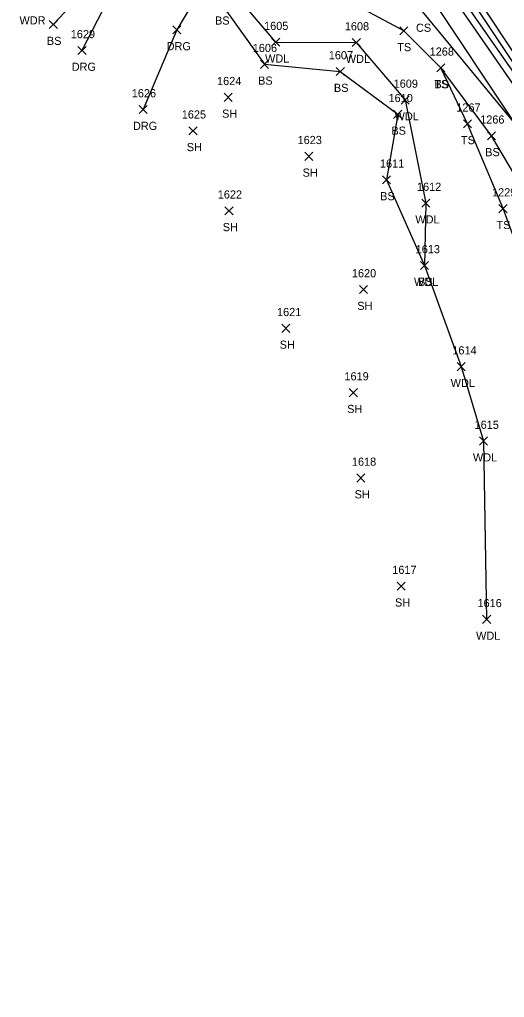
# Model space of a CAD drawing. Extents: x 1501299 to 1502485, y 381423 to 383765.
# Drawn here: x 1501632.6 to 1501751.5, y 382849.9 to 383089.7 of the extents above; entities that cross this region are included whole.
import ezdxf

# ---------------------------------------------------------------- set-up
doc = ezdxf.new("R2010")
doc.units = 0
for name, color, linetype in [('L_A', 7, 'Continuous'), ('L_I', 7, 'Continuous'), ('L_TIC', 7, 'Continuous'), ('LAWA', 7, 'Continuous'), ('LELB', 7, 'Continuous'), ('PET', 7, 'Continuous'), ('R_A', 7, 'Continuous'), ('R_I', 7, 'Continuous'), ('R_TIC', 7, 'Continuous'), ('RDG', 7, 'Continuous')]:
    doc.layers.add(name, color=color, linetype=linetype)

msp = doc.modelspace()

# ---------------------------------------------------------------- linework, layer by layer
at = {"layer": 'L_TIC'}
for points in [[(1501639.86, 383087.47), (1501641.86, 383089.47)], [(1501641.86, 383087.47), (1501639.86, 383089.47)], [(1501725.8, 383085.93), (1501727.8, 383087.93)], [(1501727.8, 383085.93), (1501725.8, 383087.93)], [(1501694.37, 383083.14), (1501696.37, 383085.14)], [(1501696.37, 383083.14), (1501694.37, 383085.14)], [(1501714.16, 383083.04), (1501716.16, 383085.04)], [(1501716.16, 383083.04), (1501714.16, 383085.04)], [(1501691.64, 383077.72), (1501693.64, 383079.72)], [(1501693.64, 383077.72), (1501691.64, 383079.72)], [(1501734.88, 383076.84), (1501736.88, 383078.84)], [(1501736.88, 383076.84), (1501734.88, 383078.84)], [(1501734.88, 383076.84), (1501736.88, 383078.84)], [(1501736.88, 383076.84), (1501734.88, 383078.84)], [(1501710.23, 383075.95), (1501712.23, 383077.95)], [(1501712.23, 383075.95), (1501710.23, 383077.95)], [(1501682.76, 383069.62), (1501684.76, 383071.62)], [(1501684.76, 383069.62), (1501682.76, 383071.62)], [(1501726.13, 383068.97), (1501728.13, 383070.97)], [(1501728.13, 383068.97), (1501726.13, 383070.97)], [(1501724.31, 383065.45), (1501726.31, 383067.45)], [(1501726.31, 383065.45), (1501724.31, 383067.45)], [(1501741.41, 383063.13), (1501743.41, 383065.13)], [(1501743.41, 383063.13), (1501741.41, 383065.13)], [(1501674.11, 383061.42), (1501676.11, 383063.42)], [(1501676.11, 383061.42), (1501674.11, 383063.42)], [(1501747.32, 383060.18), (1501749.32, 383062.18)], [(1501749.32, 383060.18), (1501747.32, 383062.18)], [(1501702.5, 383055.16), (1501704.5, 383057.16)], [(1501704.5, 383055.16), (1501702.5, 383057.16)], [(1501721.56, 383049.38), (1501723.56, 383051.38)], [(1501723.56, 383049.38), (1501721.56, 383051.38)], [(1501731.21, 383043.69), (1501733.21, 383045.69)], [(1501733.21, 383043.69), (1501731.21, 383045.69)], [(1501682.93, 383041.8), (1501684.93, 383043.8)], [(1501684.93, 383041.8), (1501682.93, 383043.8)], [(1501750.14, 383042.33), (1501752.14, 383044.33)], [(1501752.14, 383042.33), (1501750.14, 383044.33)], [(1501730.89, 383028.4), (1501732.89, 383030.4)], [(1501732.89, 383028.4), (1501730.89, 383030.4)], [(1501730.89, 383028.4), (1501732.89, 383030.4)], [(1501732.89, 383028.4), (1501730.89, 383030.4)], [(1501715.91, 383022.49), (1501717.91, 383024.49)], [(1501717.91, 383022.49), (1501715.91, 383024.49)], [(1501696.89, 383012.98), (1501698.89, 383014.98)], [(1501698.89, 383012.98), (1501696.89, 383014.98)], [(1501739.87, 383003.59), (1501741.87, 383005.59)], [(1501741.87, 383003.59), (1501739.87, 383005.59)], [(1501713.43, 382997.22), (1501715.43, 382999.22)], [(1501715.43, 382997.22), (1501713.43, 382999.22)], [(1501745.33, 382985.34), (1501747.33, 382987.34)], [(1501747.33, 382985.34), (1501745.33, 382987.34)], [(1501715.25, 382976.29), (1501717.25, 382978.29)], [(1501717.25, 382976.29), (1501715.25, 382978.29)], [(1501725.16, 382949.77), (1501727.16, 382951.77)], [(1501727.16, 382949.77), (1501725.16, 382951.77)], [(1501746.1, 382941.62), (1501748.1, 382943.62)], [(1501748.1, 382941.62), (1501746.1, 382943.62)]]:
    msp.add_lwpolyline(points, dxfattribs=at)
at = {"layer": 'LAWA'}
for points in [[(1501684.92, 383096.49), (1501695.37, 383084.14), (1501715.16, 383084.04), (1501727.13, 383069.97), (1501732.21, 383044.69), (1501731.89, 383029.4), (1501740.87, 383004.59), (1501746.33, 382986.34), (1501747.1, 382942.62)], [(1501942.68, 382714.84), (1501935.18, 382744.72), (1501913.34, 382785.2), (1501893.39, 382826.43), (1501865.29, 382869.92), (1501854.75, 382888.13), (1501835.93, 382927.55), (1501822.23, 382953.47), (1501796.61, 382993.04), (1501779.61, 383024.31), (1501754.16, 383064.05), (1501733.53, 383095.14)]]:
    msp.add_lwpolyline(points, dxfattribs=at)
at = {"layer": 'LELB'}
for points in [[(1501947.07, 382716.2), (1501936.79, 382745.62), (1501921.74, 382787.5), (1501900.17, 382829.78), (1501877.02, 382875.8), (1501866.17, 382892.91), (1501844.62, 382932.73), (1501828.06, 382959.04), (1501805.27, 382995.6), (1501783.69, 383028.16), (1501760.13, 383067.52), (1501734.81, 383103.88), (1501716.07, 383128.73), (1501702.98, 383136.28), (1501694.19, 383132.72)], [(1501947.96, 382716.12), (1501940, 382745.7), (1501923.41, 382788.32), (1501902.81, 382830.43), (1501868.96, 382893.88), (1501846.4, 382933.73), (1501830.03, 382960.15), (1501806.63, 382996.69), (1501785.68, 383029.2), (1501761.09, 383068.04), (1501736.24, 383105.32), (1501718.86, 383131.58)], [(1501945.34, 382716.14), (1501936.67, 382745.19), (1501918.39, 382786.66), (1501897.88, 382827.99), (1501871.61, 382874.07), (1501860.42, 382890.26), (1501841.87, 382931.65), (1501826.47, 382956.95), (1501803.66, 382993.76), (1501782.06, 383026.73), (1501758.57, 383066.64), (1501733.62, 383102.86), (1501712.41, 383124.49), (1501694.92, 383122.17), (1501687.27, 383121.66)], [(1501640.86, 383088.47), (1501650.74, 383098.99), (1501648.24, 383107.59)], [(1501783.59, 382899.61), (1501783.94, 382929.09), (1501780.21, 382962.68), (1501777.23, 382979.1), (1501762.26, 383002.32), (1501757.64, 383021.11), (1501754.69, 383033.79), (1501751.14, 383043.33), (1501742.41, 383064.13), (1501735.88, 383077.84), (1501726.8, 383086.93), (1501711.19, 383095.35), (1501693.41, 383100.22), (1501689.59, 383108.9)], [(1501782.08, 383006.32), (1501773.81, 383019.1), (1501754.16, 383064.05), (1501731.35, 383091.68), (1501722.18, 383098.36), (1501712.77, 383102.52), (1501700.66, 383104.88), (1501689.59, 383108.9)], [(1501680.88, 383103.61), (1501682.08, 383093.45), (1501692.64, 383078.72), (1501711.23, 383076.95), (1501725.31, 383066.45), (1501722.56, 383050.38), (1501731.89, 383029.4)], [(1501765.26, 383019.56), (1501758.79, 383034.64), (1501759.23, 383042.7), (1501748.32, 383061.18), (1501735.88, 383077.84)]]:
    msp.add_lwpolyline(points, dxfattribs=at)
at = {"layer": 'PET'}
msp.add_lwpolyline([(1501949.65, 382716.51), (1501941.04, 382745.98), (1501925.01, 382788.59), (1501904.25, 382831.62), (1501880.76, 382877.89), (1501870.56, 382894.72), (1501847.41, 382934.27), (1501830.94, 382961.01), (1501807.98, 382997.99), (1501787.08, 383029.95), (1501762.26, 383068.78), (1501737.38, 383106.29), (1501722.89, 383129.67), (1501696.7, 383166.34)], dxfattribs=at)
at = {"layer": 'R_TIC'}
for points in [[(1501670.17, 383086.16), (1501672.17, 383088.16)], [(1501672.17, 383086.16), (1501670.17, 383088.16)], [(1501646.9, 383081.12), (1501648.9, 383083.12)], [(1501648.9, 383081.12), (1501646.9, 383083.12)], [(1501661.91, 383066.62), (1501663.91, 383068.62)], [(1501663.91, 383066.62), (1501661.91, 383068.62)]]:
    msp.add_lwpolyline(points, dxfattribs=at)
at = {"layer": 'RDG'}
for points in [[(1501662.06, 383199.17), (1501675.11, 383176.66), (1501684.59, 383158.08), (1501685.54, 383149.23), (1501676.08, 383131.44), (1501669.33, 383121.4), (1501658.13, 383102.11), (1501647.9, 383082.12)], [(1501722.89, 383129.67), (1501718.86, 383131.58), (1501701.9, 383140.13), (1501694.19, 383132.72), (1501687.27, 383121.66), (1501682.68, 383110.73), (1501680.88, 383103.61), (1501671.17, 383087.16), (1501662.91, 383067.62)]]:
    msp.add_lwpolyline(points, dxfattribs=at)

# ---------------------------------------------------------------- texts
at = {"layer": 'L_A'}
for s, p in [('WDR', (1501632.58, 383088.49)), ('BS', (1501680.52, 383088.45)), ('CS', (1501729.79, 383086.68)), ('BS', (1501639.3, 383083.47)), ('TS', (1501725.21, 383081.93)), ('WDL', (1501692.79, 383079.14)), ('WDL', (1501712.58, 383079.04)), ('BS', (1501691.08, 383073.72)), ('BS', (1501709.67, 383071.95)), ('TS', (1501734.29, 383072.84)), ('BS', (1501734.32, 383072.84)), ('SH', (1501682.25, 383065.62)), ('WDL', (1501724.55, 383064.97)), ('BS', (1501723.75, 383061.45)), ('SH', (1501673.6, 383057.42)), ('TS', (1501740.82, 383059.13)), ('BS', (1501746.76, 383056.18)), ('SH', (1501701.99, 383051.16)), ('BS', (1501721, 383045.38)), ('WDL', (1501729.63, 383039.69)), ('TS', (1501749.55, 383038.33)), ('SH', (1501682.42, 383037.8)), ('WDL', (1501729.3, 383024.4)), ('BS', (1501730.33, 383024.4)), ('SH', (1501715.4, 383018.49)), ('SH', (1501696.38, 383008.98)), ('WDL', (1501738.29, 382999.59)), ('SH', (1501712.92, 382993.22)), ('WDL', (1501743.75, 382981.34)), ('SH', (1501714.74, 382972.29)), ('SH', (1501724.65, 382945.77)), ('WDL', (1501744.52, 382937.62))]:
    msp.add_text(s, height=2, dxfattribs=at).set_placement(p)
at = {"layer": 'L_I'}
for s, p in [('1605', (1501692.55, 383087.14)), ('1608', (1501712.34, 383087.04)), ('1606', (1501689.77, 383081.72)), ('1607', (1501708.41, 383079.95)), ('1268', (1501733.14, 383080.84)), ('1268', (1501733.14, 383080.84)), ('1624', (1501681.02, 383073.62)), ('1609', (1501724.31, 383072.97)), ('1610', (1501723.05, 383069.45)), ('1267', (1501739.67, 383067.13)), ('1625', (1501672.37, 383065.42)), ('1266', (1501745.53, 383064.18)), ('1623', (1501700.76, 383059.16)), ('1611', (1501720.95, 383053.38)), ('1612', (1501730.03, 383047.69)), ('1622', (1501681.19, 383045.8)), ('1229', (1501748.44, 383046.33)), ('1613', (1501729.71, 383032.4)), ('1613', (1501729.71, 383032.4)), ('1620', (1501714.08, 383026.49)), ('1621', (1501695.72, 383016.98)), ('1614', (1501738.7, 383007.59)), ('1619', (1501712.25, 383001.22)), ('1615', (1501744.16, 382989.34)), ('1618', (1501714.08, 382980.29)), ('1617', (1501723.98, 382953.77)), ('1616', (1501744.87, 382945.62))]:
    msp.add_text(s, height=2, dxfattribs=at).set_placement(p)
at = {"layer": 'R_A'}
for p in [(1501668.66, 383082.16), (1501645.38, 383077.12), (1501660.4, 383062.62)]:
    msp.add_text('DRG', height=2, dxfattribs=at).set_placement(p)
at = {"layer": 'R_I'}
for s, p in [('1629', (1501645.15, 383085.12)), ('1626', (1501660.11, 383070.62))]:
    msp.add_text(s, height=2, dxfattribs=at).set_placement(p)

doc.saveas('drawing.dxf')
